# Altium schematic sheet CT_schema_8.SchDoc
size 277 x 170 mm
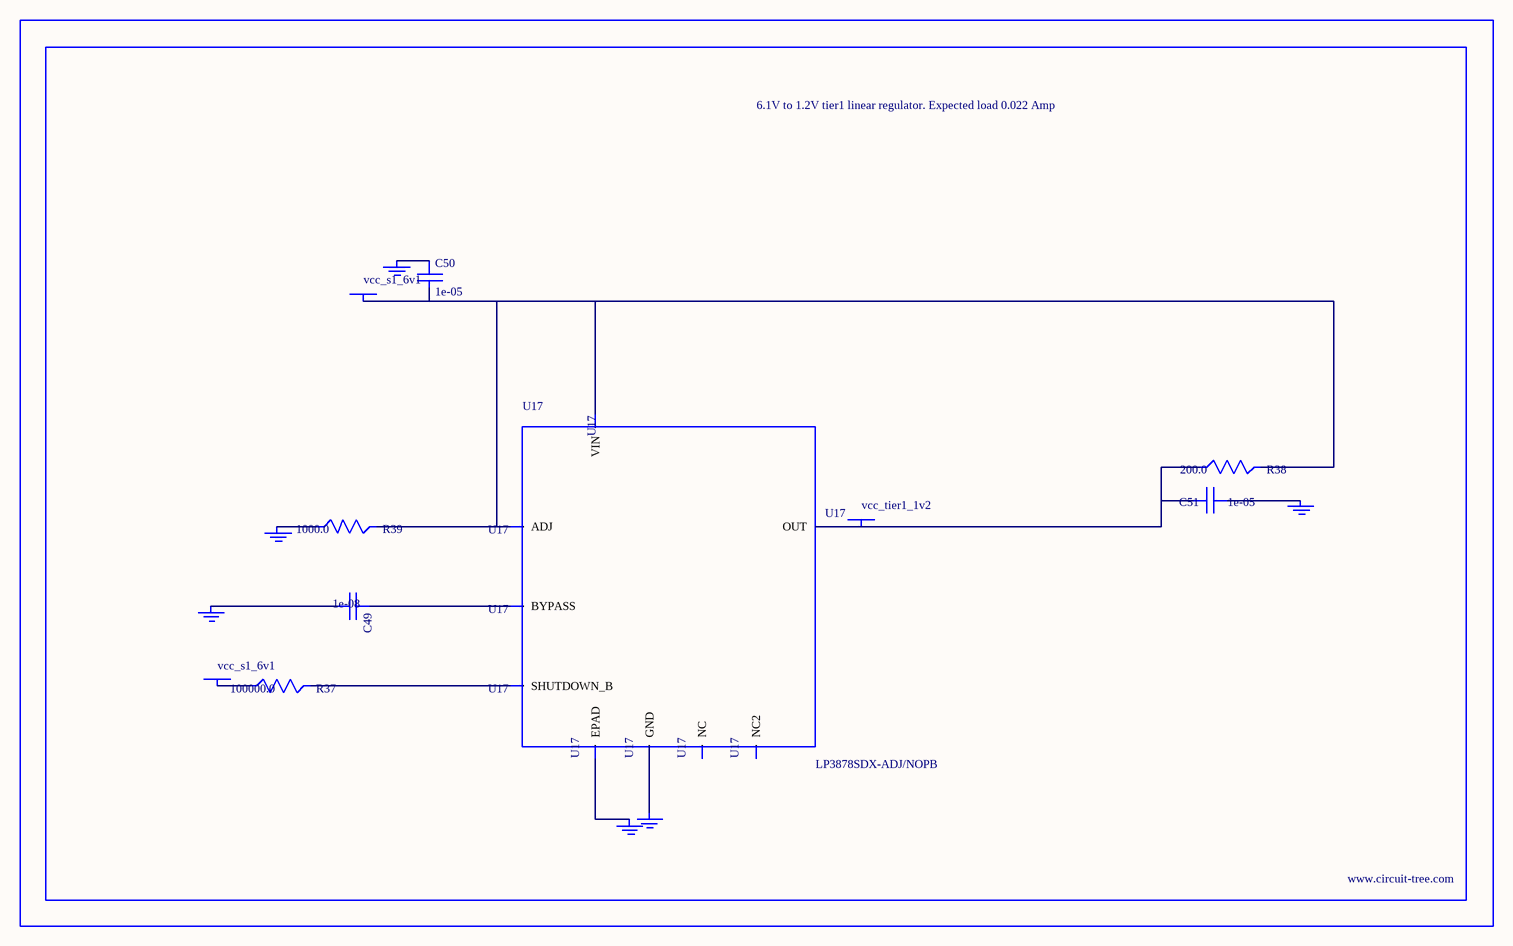
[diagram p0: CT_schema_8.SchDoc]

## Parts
BORDER7  (no value)
C49  1e-08  [C0402]
C50  1e-05  [C1206]
C51  1e-05  [C0805]
GND_INSTANCE_7_0  (no value)
GND_INSTANCE_7_1  (no value)
GND_INSTANCE_7_2  (no value)
GND_INSTANCE_7_3  (no value)
GND_INSTANCE_7_4  (no value)
GND_INSTANCE_7_5  (no value)
POWER_INSTANCE_7_0  vcc_s1_6v1
POWER_INSTANCE_7_1  vcc_s1_6v1
POWER_INSTANCE_7_2  vcc_tier1_1v2
R37  100000.0  [R0603]
R38  200.0  [R0603]
R39  1000.0  [R0603]
U17  LP3878SDX-ADJ/NOPB  [WSON-8]

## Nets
NetC49_1: C49.1 U17.1(BYPASS)
NetC49_2: C49.2 GND_INSTANCE_7_0.0(GND)
NetC50_1: C50.1 GND_INSTANCE_7_1.0(GND)
NetC50_2: C50.2 POWER_INSTANCE_7_0.0(PWR) R38.2 R39.2 U17.4(VIN) U17.6(ADJ)
NetC51_1: C51.1 GND_INSTANCE_7_2.0(GND)
NetC51_2: C51.2 POWER_INSTANCE_7_2.0(PWR) R38.1 U17.5(OUT)
NetGND_INSTANCE_7_3_0: GND_INSTANCE_7_3.0(GND) R39.1
NetGND_INSTANCE_7_4_0: GND_INSTANCE_7_4.0(GND) U17.PAD(EPAD)
NetGND_INSTANCE_7_5_0: GND_INSTANCE_7_5.0(GND) U17.3(GND)
NetPOWER_INSTANCE_7_1_0: POWER_INSTANCE_7_1.0(PWR) R37.1
NetR37_2: R37.2 U17.8(SHUTDOWN_B)

Not connected (* = marked no-connect by the designer): U17 2(NC) 7(NC2)

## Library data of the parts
BORDER7 = BORDER_PAGE7
C49 = C0402C103K3RAC
C50 = C1206C106K3RACTU
C51 = GRM219R60J106ME19D
GND_INSTANCE_7_0-GND_INSTANCE_7_5 = GND
POWER_INSTANCE_7_0-POWER_INSTANCE_7_2 = PWR
R37 = RC0603JR-07100KL
R38 = RC0603JR-07200RL
R39 = RC0603JR-071KL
